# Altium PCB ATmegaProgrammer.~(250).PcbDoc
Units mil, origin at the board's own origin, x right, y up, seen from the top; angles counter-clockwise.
Board outline 2130 x 2300 mil, 2 copper layers (Top Layer, Bottom Layer); 13 components, 10 nets, 72 pads, 0 vias.
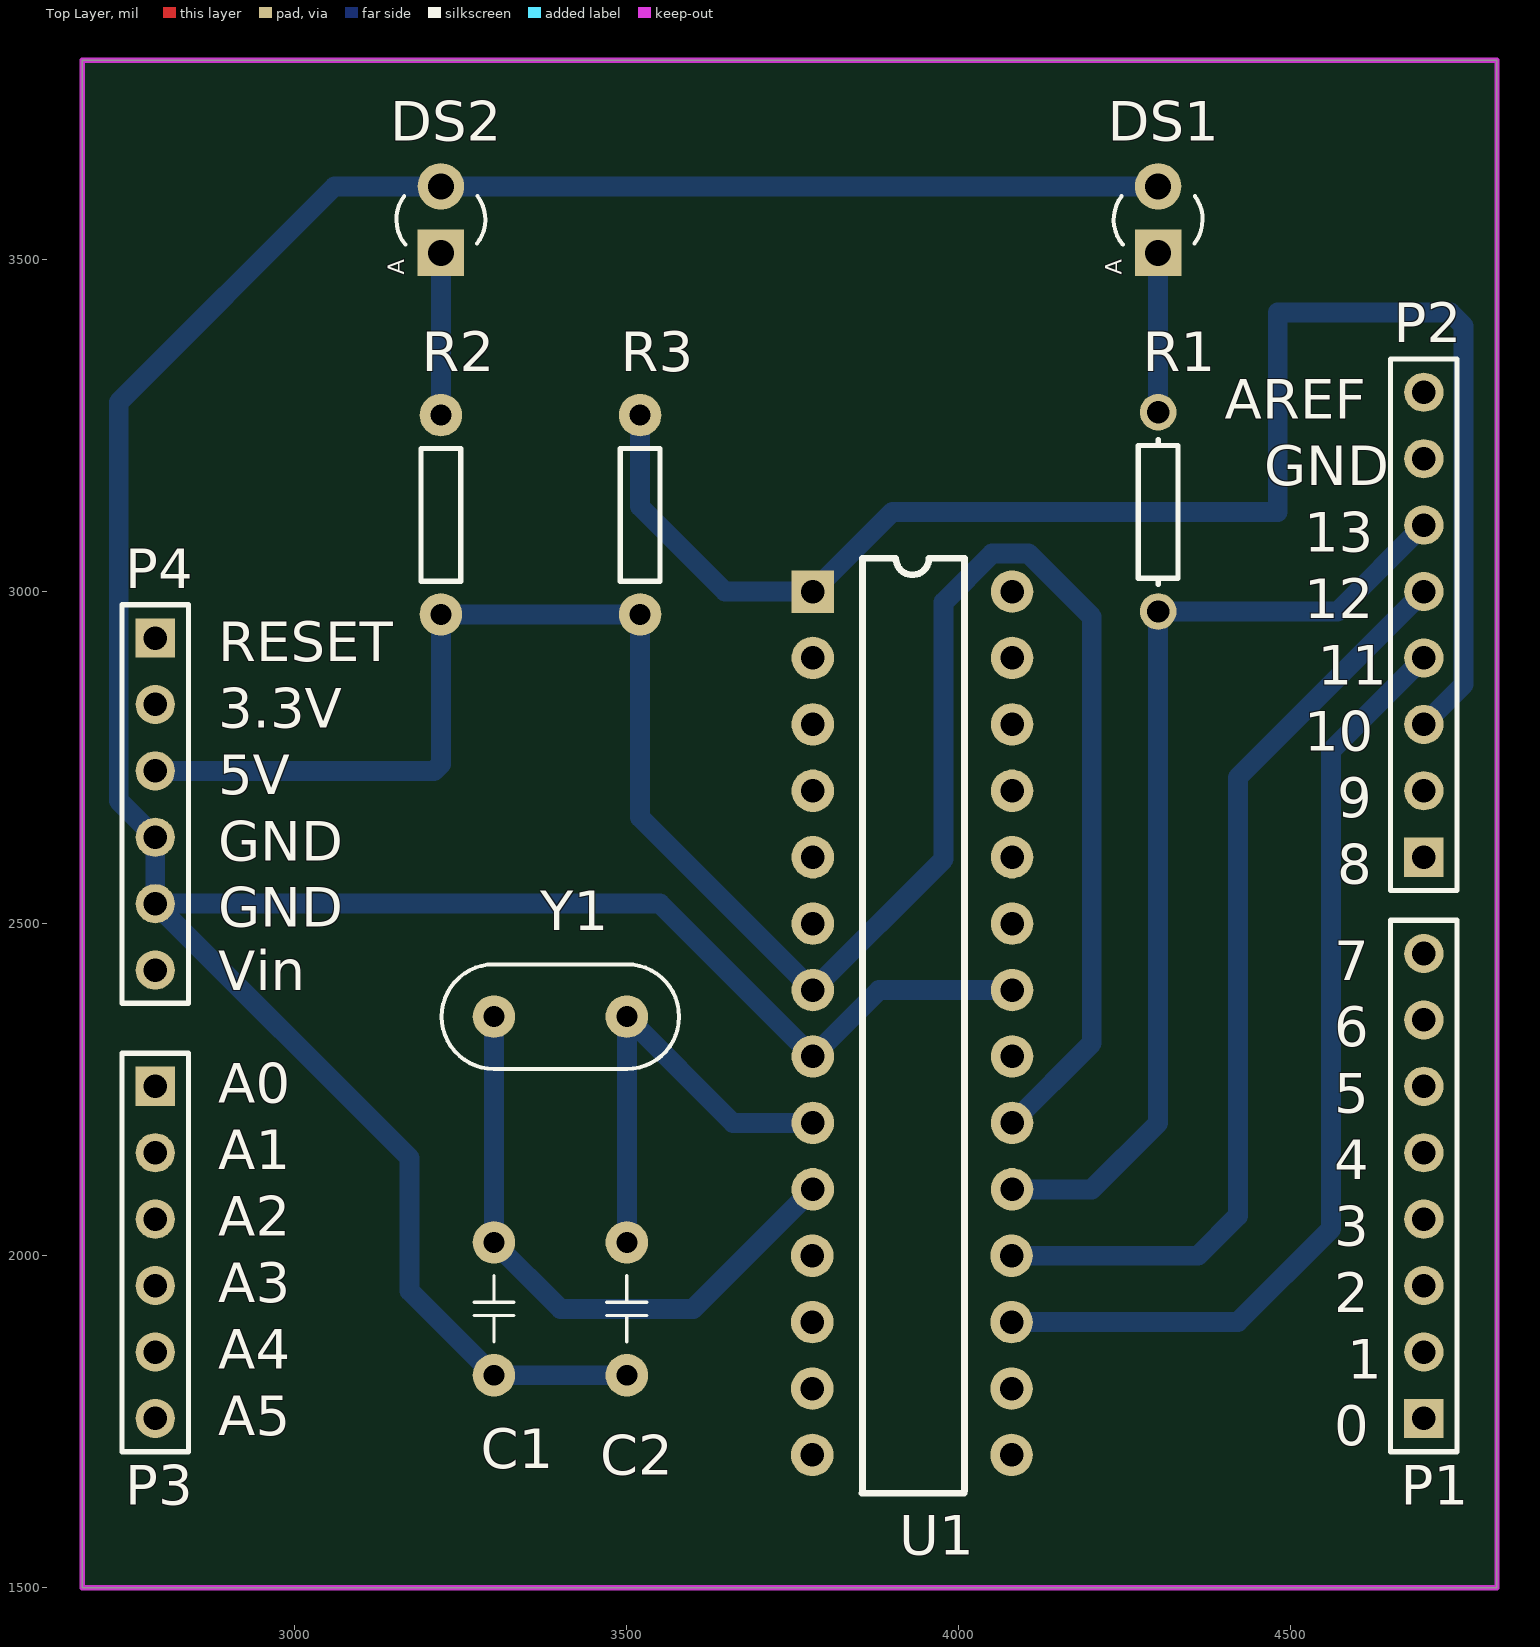
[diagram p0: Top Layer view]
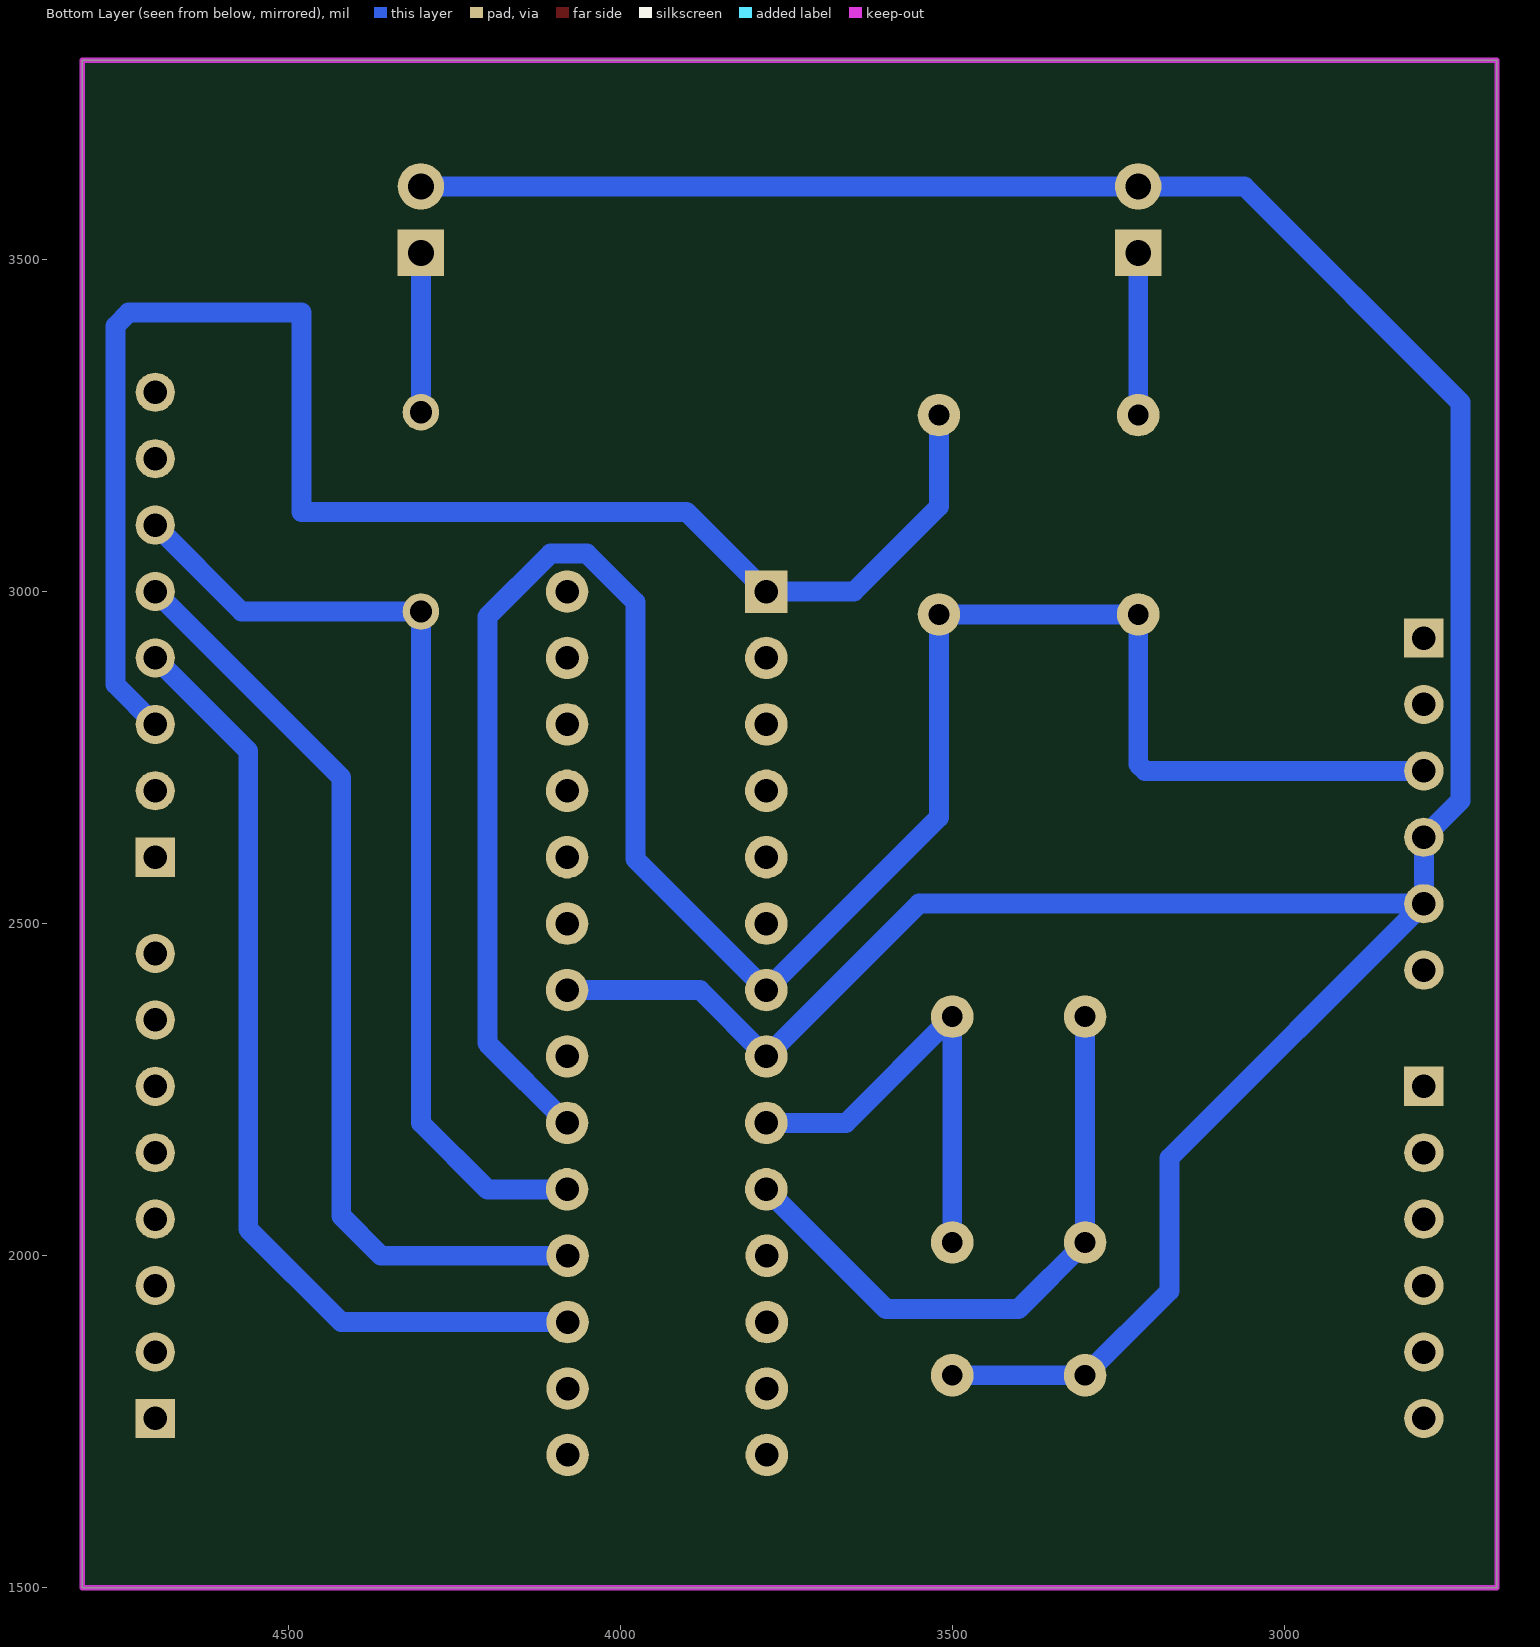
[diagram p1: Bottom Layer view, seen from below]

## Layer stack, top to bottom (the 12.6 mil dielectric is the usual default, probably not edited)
Top Layer: signal copper 1.4
Dielectric: dielectric 12.6, FR-4, Dk 4.8
Bottom Layer: signal copper 1.4

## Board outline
2680,1500 2680,3800 4810,3800 4810,1500

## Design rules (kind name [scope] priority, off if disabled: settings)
Clearance [All] p1: gap=10
PolygonConnect [All] p1: connectstyle=Relief reliefconductorwidth=10 reliefentries=4 polygonreliefangle="90 Angle"
RoutingLayers [All] p1: top layer_v5=FALSE bottom layer_v5=TRUE
RoutingVias [All] p1: holewidth=28 width=50 viastyle="Through Hole" minholewidth=28 minwidth=50 maxholewidth=28 maxwidth=50
SilkscreenOverComponentPads [All] p1: minsilkscreentomaskgap=10
SolderMaskExpansion [All] p1: expansion=4
Width VCC [All] p1: maxlimit=40 minlimit=20 preferedwidth=30
Width GND [InNet('GND')] p2: maxlimit=40 minlimit=20 preferedwidth=30
Width [All] p3: maxlimit=40 minlimit=10 preferedwidth=30
26 further rules are at their usual default settings.

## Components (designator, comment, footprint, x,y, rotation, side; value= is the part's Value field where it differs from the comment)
C1 "20pF" C200 3300,1920 r180 top
C2 "20pF" C200 3500,1920 r180 top
DS1 "LED" LED-3mm_G 4300,3560 r90 top
DS2 "LED" LED-3mm_G 3220,3560 r90 top
P1 "Header 8" HDR1X8 4700,1755 r90 top
P2 "Header 8" HDR1X8 4700,2600 r90 top
P3 "Header 6" HDR1X6 2790,2255 r270 top
P4 "Header 6" HDR1X6 2790,2930 r270 top
R1 "Res1" AXIAL-0.3#1 4300,3120 r270 top
R2 "220" AXIAL-0.3#2 3220,3115.56 r270 top
R3 "10k" AXIAL-0.3#2 3520,3115.56 r270 top
U1 "ATmega328" DIP-28 3780,3000 r270 top
Y1 "16MHz" XTAL4-8 3400,2360 r180 top

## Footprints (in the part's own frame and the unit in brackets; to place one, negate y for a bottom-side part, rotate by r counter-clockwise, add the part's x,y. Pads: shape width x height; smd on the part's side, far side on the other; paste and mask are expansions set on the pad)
AXIAL-0.3#1 [mm] "Axial Device, Thru-Hole; 2 Leads; 0.3 in Pin Spacing"
  round 1.4 hole 0.85: 1(-3.81,0) 2(3.81,0)
  silkscreen extent -2.77,-0.76 2.77,0.76
AXIAL-0.3#2 [mm] "0.3\" Resistor; 2 Leads"
  round 1.626 hole 0.8: 1(-3.81,0) 2(3.81,0)
  silkscreen extent -2.54,-0.76 2.54,0.76, body extent -4.1,-1 4.19,1, height 2.19
C200 [mil] "鹅溅筿甧竟"
  round 64 hole 31.5: 1(0,100) 2(0,-100)
  silkscreen extent -30,-50 30,50, body extent -41,-136 39,135, height 354
DIP-28 [mil]
  rect 64x64 hole 35.43: 1(0,0)
  round 64 hole 35.43: 2(100,0) 3(200,0) 4(300,0) 5(400,0) 6(500,0) 7(600,0) 8(700,0) 9(800,0) 10(900,0) 11(1000,-0.79) 12(1100,-0.79) 13(1200,-0.79) 14(1300,-0.79) 15(1300,299.21) 16(1200,299.21) 17(1100,299.21) 18(1000,299.21) 19(900,300) 20(800,300) 21(700,300) 22(600,300) 23(500,300) 24(400,300) 25(300,300) 26(200,300) 27(100,300) 28(0,300)
  silkscreen extent -50,74 1358,228, body extent -53,-5 1358,304, height 209
HDR1X6 [mm] "Connector; Header; 6 Position"
  rect 1.5x1.5 hole 0.9: 1(0,0)
  round 1.5 hole 0.9: 2(2.54,0) 3(5.08,0) 4(7.62,0) 5(10.16,0) 6(12.7,0)
  silkscreen extent -1.27,-1.27 13.97,1.27
HDR1X8 [mm] "Connector; Header; 8 Position"
  rect 1.5x1.5 hole 0.9: 1(0,0)
  round 1.5 hole 0.9: 2(2.54,0) 3(5.08,0) 4(7.62,0) 5(10.16,0) 6(12.7,0) 7(15.24,0) 8(17.78,0)
  silkscreen extent -1.27,-1.27 19.05,1.27
LED-3mm_G [mil] "3mm LED_Green"
  rect 70x70 hole 39: 1(-50,0)
  round 70 hole 39: 2(50,0)
  silkscreen extent -38,-67 35,67, body extent -66,-68 67,66, height 181
XTAL4-8 [mil]
  round 64 hole 31.5: 1(-100,0) 2(100,0)
  silkscreen extent -179,-79 179,79, body extent -178,-80 192,79, height 157

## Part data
C1 C2: library part Cap, "Capacitor"
DS1 DS2: "Typical INFRARED GaAs LED"
P1 P2: "Header, 8-Pin"
P3 P4: "Header, 6-Pin"
R1: "Resistor"
R2 R3: library part Res, "Resistor"
U1: "Arduino"
Y1: library part XTAL, "Crystal Oscillator"

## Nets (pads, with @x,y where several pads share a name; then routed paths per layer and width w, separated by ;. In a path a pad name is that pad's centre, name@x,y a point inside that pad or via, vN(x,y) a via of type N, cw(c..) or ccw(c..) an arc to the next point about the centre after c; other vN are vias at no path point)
GND: C1.1 C2.1 DS1.2 DS2.2 P4.4 P4.5 U1.8 U1.22 | length 5025.3
  Bottom Layer w30: C2.1 C1.1 3173,1947 3173,2147 P4.5 ; U1.22 3880,2400 U1.8 3550,2530 P4.5 ; DS1.2 DS2.2 3060,3610 2735,3285 2735,2685 P4.4 P4.5
MISO: P2.5 U1.18 | length 1421.6
  Bottom Layer w30: U1.18 4360,2000 4420,2060 4420,2720 P2.5
MOSI: P2.4 U1.17 | length 1456.8
  Bottom Layer w30: U1.17 4420,1900 4560,2040 4560,2760 P2.4
NetC1_2: C1.2 U1.10 Y1.2 | length 936
  Bottom Layer w30: Y1.2 C1.2 3400,1920 3600,1920 U1.10
NetC2_2: C2.2 U1.9 Y1.1 | length 686.3
  Bottom Layer w30: C2.2 Y1.1 3660,2200 U1.9
NetDS1_1: DS1.1 R1.1 | length 230
  Bottom Layer w30: R1.1@4300,3280 DS1.1
NetDS2_1: DS2.1 R2.1 | length 244.4
  Bottom Layer w30: R2.1 DS2.1
RESET: P2.3 R3.1 U1.1 | length 2413.4
  Bottom Layer w30: R3.1 3520,3128 3648,3000 U1.1 3900,3120 4480,3120 4480,3420 4740,3420 4760,3400 4760,2860 P2.3
SCK: P2.6 R1.2 U1.19 | length 1485.3
  Bottom Layer w30: U1.19 4200,2100 4300,2200 R1.2 4570,2970 P2.6
VCC: P4.3 R2.2 R3.2 U1.7 U1.20 | length 3402.8
  Bottom Layer w30: P4.3 3210,2730 3220,2740 R2.2 R2.2@3220,2950 ; R2.2@3235.56,2965.56 R3.2 3520,2660 U1.7 3977,2597 3977,2984 4050,3057 4105,3057 4200,2962 4200,2320 U1.20
pads on no net: P1.1 P1.2 P1.3 P1.4 P1.5 P1.6 P1.7 P1.8 P2.1 P2.2 P2.7 P2.8 P3.1 P3.2 P3.3 P3.4 P3.5 P3.6 P4.1 P4.2 P4.6 U1.2 U1.3 U1.4 U1.5 U1.6 U1.11 U1.12 U1.13 U1.14 U1.15 U1.16 U1.21 U1.23 U1.24 U1.25 U1.26 U1.27 U1.28

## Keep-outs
Keep-Out Layer:
  the board outline again, w7.87

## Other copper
Bottom Layer:
  text "AtProgrammer" at 5160,3600 h60 r90

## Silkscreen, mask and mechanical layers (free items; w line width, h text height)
Top Overlay:
  lines w7.87: 0,0 0,200 ; 20,0 35,0 ; 55,0 195,0 ; 2740,1705 2740,1713.25
  text "AREF" at 4400.02,3260 h60
  text "GND" at 4460,3160 h60
  text "13" at 4519.96,3060 h60
  text "12" at 4519.96,2960 h60
  text "RESET" at 2885.05,2895 h60
  text "11" at 4539.95,2860 h60
  text "3.3V" at 2885.05,2795 h60
  text "10" at 4519.96,2760 h60
  text "5V" at 2885.05,2695 h60
  text "9" at 4569.94,2660 h60
  text "GND" at 2885.05,2595 h60
  text "8" at 4569.94,2560 h60
  text "GND" at 2885.05,2495 h60
  text "7" at 4564.94,2415 h60
  text "Vin" at 2885.05,2400 h60
  text "6" at 4564.94,2315 h60
  text "A0" at 2885.05,2230 h60
  text "5" at 4564.94,2215 h60
  text "A1" at 2885.05,2130 h60
  text "4" at 4564.94,2115 h60
  text "A2" at 2885.05,2030 h60
  text "3" at 4564.94,2015 h60
  text "A3" at 2885.05,1930 h60
  text "2" at 4564.94,1915 h60
  text "A4" at 2885.05,1830 h60
  text "1" at 4584.94,1815 h60
  text "A5" at 2885.05,1730 h60
  text "0" at 4564.94,1715 h60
